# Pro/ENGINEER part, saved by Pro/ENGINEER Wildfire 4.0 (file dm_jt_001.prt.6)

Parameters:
  METRIC = "NO"

Other parameters: PITCH, DRILL_DIAMETER, THREAD_DIAMETER, THREADS_PER_INCH, THREAD_DEPTH, THREAD_LENGTH, DRILL_POINT_ANGLE, DRILL_DEPTH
